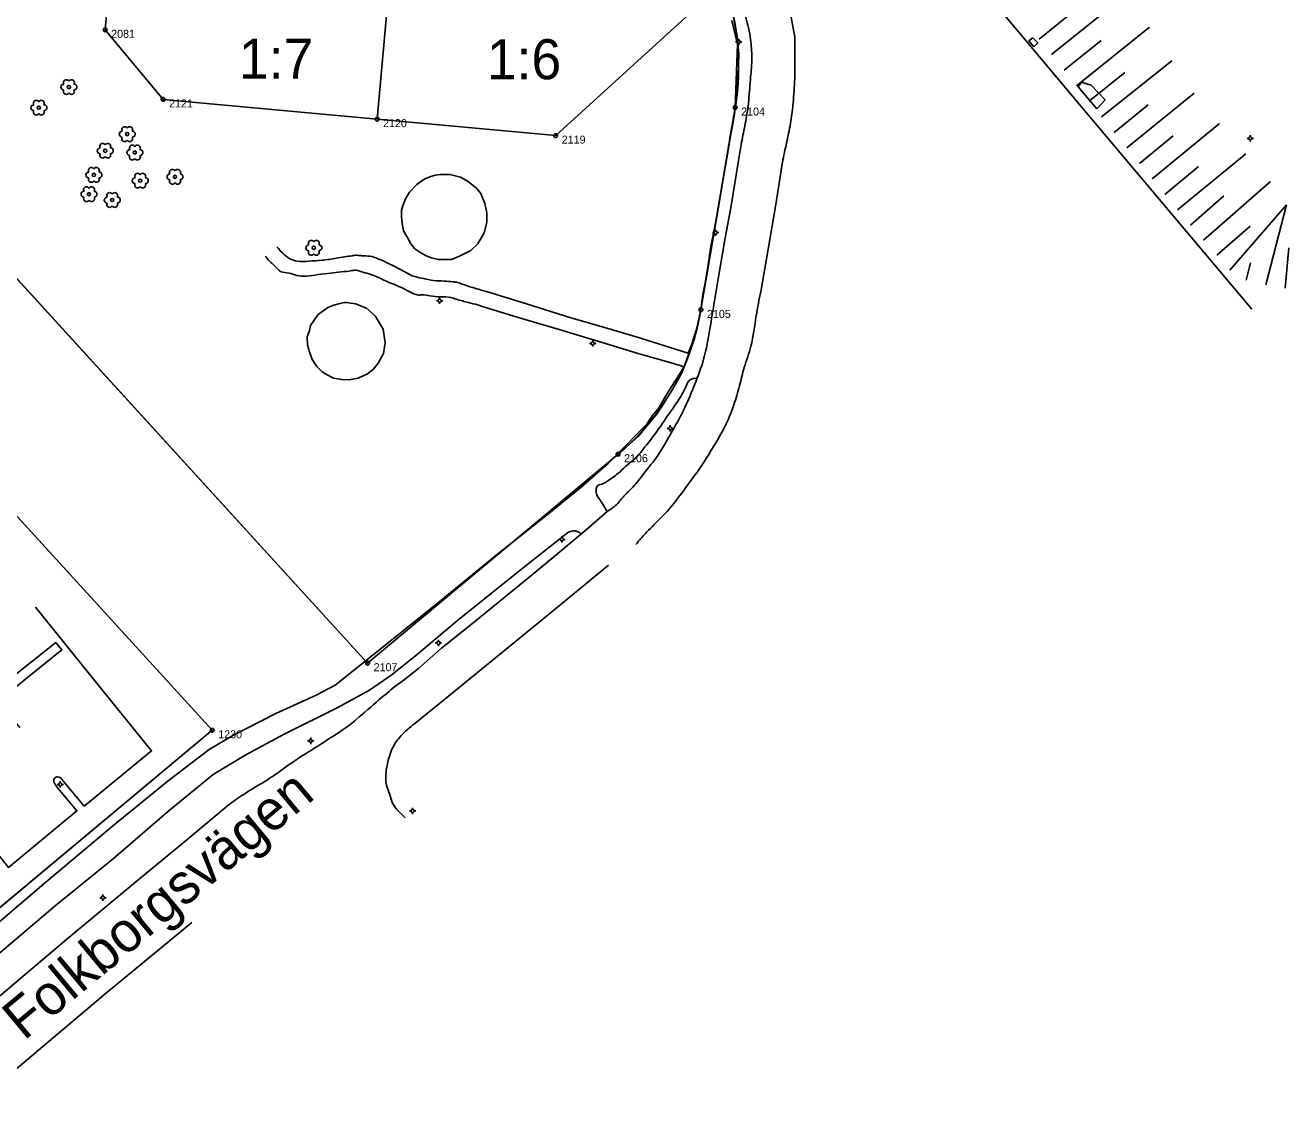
# Model space of a CAD drawing. Extents: x 1517478 to 1518189, y 6494860 to 6495389.
# Drawn here: x 1518031.3 to 1518189.2, y 6494972.1 to 6495107.4 of the extents above; entities that cross this region are included whole.
import ezdxf

# ---------------------------------------------------------------- set-up
doc = ezdxf.new("R2010")
doc.units = 0
for name, color, linetype in [('fastighetsbeteckning', 7, 'Continuous'), ('gatunamn', 7, 'Continuous'), ('gc_vag', 7, 'Continuous'), ('grans', 7, 'Continuous'), ('granspunkt', 7, 'Continuous'), ('granspunkt_text', 7, 'Continuous'), ('kvartersgrans', 7, 'Continuous'), ('kvartersgrans_utan_fastgr', 7, 'Continuous'), ('kvartersytor', 7, 'Continuous'), ('lovtrad', 7, 'Continuous'), ('parkeringskant', 7, 'Continuous'), ('planteringskant', 7, 'Continuous'), ('slant_skraffering', 7, 'Continuous'), ('staket', 7, 'Continuous'), ('stolpe_belysning', 7, 'Continuous'), ('vagkant', 7, 'Continuous')]:
    doc.layers.add(name, color=color, linetype=linetype)

msp = doc.modelspace()

# ---------------------------------------------------------------- linework, layer by layer
at = {"layer": 'gc_vag'}
for points in [[(1518118.38, 6495087.34), (1518118.71, 6495089.22), (1518119.1, 6495091.32), (1518119.41, 6495093.33), (1518119.63, 6495094.49)], [(1518116.59, 6495076.95), (1518117.01, 6495079.78), (1518117.66, 6495083.14), (1518118.07, 6495085.6), (1518118.38, 6495087.34)], [(1518108.34, 6495068.28), (1518114.17, 6495066.44), (1518114.67, 6495067.72), (1518115.19, 6495069.34), (1518115.54, 6495070.77), (1518115.78, 6495072.17), (1518116, 6495073.78), (1518116.31, 6495075.24), (1518116.59, 6495076.95)], [(1518089.11, 6495074.12), (1518093.31, 6495072.82), (1518099.4, 6495070.92), (1518104, 6495069.59), (1518108.36, 6495068.28)], [(1518088.71, 6495072.21), (1518092.82, 6495070.95), (1518098.04, 6495069.4), (1518103.85, 6495067.66), (1518108.04, 6495066.38)], [(1518108.04, 6495066.38), (1518111.18, 6495065.48), (1518113.3, 6495064.86), (1518113.64, 6495064.7), (1518112.86, 6495063.49), (1518112.15, 6495062.31), (1518111.37, 6495061.1), (1518110.56, 6495059.64), (1518109.72, 6495058.67), (1518108.98, 6495057.52), (1518108.11, 6495056.71)], [(1518070.06, 6495024.95), (1518076.25, 6495029.91), (1518083.28, 6495035.51), (1518090.37, 6495041.36), (1518096.55, 6495046.25), (1518100.78, 6495049.7), (1518104.23, 6495052.69), (1518108.11, 6495056.71)], [(1518099.11, 6495043.98), (1518092.97, 6495039.15), (1518085.36, 6495033.03), (1518080.35, 6495028.8), (1518077.16, 6495026.26), (1518074.33, 6495024.31)], [(1518049.18, 6495012.98), (1518054.3, 6495016.9), (1518057.26, 6495018.64), (1518062.65, 6495021.42), (1518067.69, 6495023.69), (1518070.06, 6495024.95)], [(1518049.31, 6495009.27), (1518054.82, 6495013.77), (1518058.82, 6495016.21), (1518063.69, 6495018.82), (1518070.3, 6495022.12), (1518074.33, 6495024.31)], [(1518018.32, 6494987.11), (1518024.97, 6494992.73), (1518033.63, 6495000.09), (1518042.48, 6495007.51), (1518049.18, 6495012.98)], [(1518025.3, 6494989.09), (1518035.06, 6494997.36), (1518042.35, 6495003.28), (1518049.31, 6495009.27)]]:
    msp.add_lwpolyline(points, dxfattribs=at)
for points in [[(1518112.4, 6495123.17), (1518115.62, 6495119.07), (1518117.64, 6495115.15), (1518118.65, 6495112.85), (1518119.88, 6495108.19), (1518120.44, 6495104.77), (1518120.39, 6495101.02)], [(1518120.39, 6495101.02), (1518120.02, 6495096.76), (1518119.35, 6495093.11), (1518118.85, 6495090.03)], [(1518062.77, 6495079.75), (1518063.52, 6495078.94), (1518064.39, 6495078.26), (1518065.32, 6495077.95), (1518066.75, 6495077.95), (1518068.43, 6495078.07), (1518070.17, 6495078.32), (1518071.23, 6495078.51), (1518072.16, 6495078.63), (1518072.78, 6495078.69), (1518073.4, 6495078.63), (1518074.4, 6495078.57), (1518075.39, 6495078.26), (1518076.32, 6495077.89)], [(1518088.99, 6495072.13), (1518086.72, 6495072.79), (1518085.2, 6495073.19), (1518084.51, 6495073.41), (1518083.27, 6495073.5), (1518081.87, 6495073.63), (1518080.97, 6495073.75), (1518080.47, 6495073.72), (1518079.88, 6495073.88), (1518078.58, 6495074.53), (1518076.65, 6495075.37), (1518074.29, 6495076.36), (1518073.26, 6495076.67), (1518072.74, 6495076.83), (1518072.14, 6495076.77), (1518070.78, 6495076.61), (1518069.5, 6495076.46), (1518067.92, 6495076.27), (1518066.49, 6495076.08), (1518065.28, 6495076.18), (1518064.28, 6495076.46), (1518063.29, 6495076.64), (1518062.85, 6495076.98), (1518062.17, 6495077.67), (1518061.8, 6495078.01), (1518061.36, 6495078.57)], [(1518076.25, 6495077.92), (1518078.76, 6495076.61), (1518080.01, 6495076.02), (1518081.13, 6495075.77), (1518082.34, 6495075.55), (1518083.64, 6495075.46), (1518084.76, 6495075.37), (1518085.35, 6495075.28), (1518086.1, 6495075.03), (1518087.96, 6495074.44), (1518089.3, 6495074.06)], [(1518104.03, 6495046.64), (1518103.2, 6495048.02), (1518102.76, 6495048.73), (1518102.66, 6495049.33), (1518102.82, 6495049.85), (1518103.37, 6495050.09), (1518104.49, 6495050.72), (1518105.66, 6495051.63), (1518106.59, 6495052.5), (1518107.55, 6495053.3), (1518108.56, 6495054.45), (1518110.25, 6495056.66), (1518112, 6495059.2), (1518113.24, 6495061.03), (1518113.82, 6495062.13), (1518114.48, 6495063.17), (1518114.93, 6495063.3), (1518115.29, 6495063.32)], [(1518100.81, 6495043.84), (1518100.4, 6495044.12), (1518099.93, 6495044.23), (1518099.36, 6495044.12), (1518099.11, 6495043.98)]]:
    msp.add_spline(points, degree=3, dxfattribs=at)
at = {"layer": 'grans'}
for p, q in [((1517942.78, 6495142.01), (1518054.69, 6495019.3)), ((1518041.31, 6495106.88), (1518042.65, 6495121.42)), ((1518077.26, 6495117.12), (1518075.29, 6495095.71)), ((1518118.64, 6495112.82), (1518097.62, 6495093.65)), ((1518048.54, 6495098.18), (1518041.31, 6495106.88)), ((1518075.29, 6495095.71), (1518048.54, 6495098.18)), ((1518097.62, 6495093.65), (1518075.29, 6495095.71)), ((1517998.49, 6494972.4), (1518054.69, 6495019.3))]:
    msp.add_line(p, q, dxfattribs=at)
at = {"layer": 'granspunkt'}
for centre in [(1518041.31, 6495106.88), (1518048.54, 6495098.18), (1518120.04, 6495097.16), (1518075.29, 6495095.71), (1518097.62, 6495093.65), (1518115.77, 6495071.86), (1518105.41, 6495053.82), (1518074.11, 6495027.69), (1518054.69, 6495019.3)]:
    msp.add_circle(centre, 0.237, dxfattribs=at)
at = {"layer": 'kvartersgrans'}
msp.add_line((1517998.49, 6494972.4), (1518054.69, 6495019.3), dxfattribs=at)
msp.add_lwpolyline([(1517905.68, 6495182.68), (1517942.78, 6495142.01), (1518054.69, 6495019.3)], dxfattribs=at)
at = {"layer": 'kvartersgrans_utan_fastgr'}
for p, q in [((1517921.04, 6495195.52), (1518074.11, 6495027.69)), ((1518115.77, 6495071.86), (1518120.04, 6495097.16)), ((1518074.11, 6495027.69), (1518105.41, 6495053.82))]:
    msp.add_line(p, q, dxfattribs=at)
for centre, radius, start, end in [((1518089.47, 6495102.32), 31.01, 350.4256, 19.8012), ((1518086.18, 6495076.85), 30.01, 309.8505, 350.4132)]:
    msp.add_arc(centre, radius, start, end, dxfattribs=at)
at = {"layer": 'kvartersytor'}
for points in [[(1518119.61, 6495108.06), (1518120.35, 6495105.08), (1518120.04, 6495097.16), (1518117.91, 6495084.51), (1518115.77, 6495071.86), (1518114.98, 6495068.27), (1518113.39, 6495063.98), (1518112.21, 6495061.91), (1518110.29, 6495058.89), (1518107.91, 6495056.05), (1518105.41, 6495053.81), (1518074.11, 6495027.69), (1517921.04, 6495195.52)], [(1517905.68, 6495182.68), (1518054.69, 6495019.3), (1517998.49, 6494972.4)]]:
    msp.add_lwpolyline(points, dxfattribs=at)
at = {"layer": 'lovtrad'}
for centre in [(1518036.78, 6495099.72), (1518033.02, 6495097.14), (1518044.06, 6495093.84), (1518041.32, 6495091.76), (1518045.02, 6495091.54), (1518039.9, 6495088.74), (1518045.69, 6495088.02), (1518050.04, 6495088.5), (1518039.29, 6495086.33), (1518042.19, 6495085.6), (1518067.38, 6495079.63)]:
    msp.add_circle(centre, 0.2, dxfattribs=at)
for centre, start, end in [((1518036.15, 6495099.72), 89.5389, 268.9887), ((1518036.46, 6495100.28), 29.1347, 212.3057), ((1518037.1, 6495100.28), 329.1331, 150.8613), ((1518037.42, 6495099.72), 269.1508, 90.8733), ((1518036.46, 6495099.17), 150.5831, 330.865), ((1518037.1, 6495099.17), 209.1844, 30.8583), ((1518032.39, 6495097.14), 89.5389, 268.9887), ((1518032.7, 6495097.7), 29.1347, 212.3057), ((1518033.34, 6495097.7), 329.1331, 150.8613), ((1518033.66, 6495097.14), 269.1508, 90.8733), ((1518032.7, 6495096.59), 150.5831, 330.865), ((1518033.34, 6495096.59), 209.1844, 30.8583), ((1518043.43, 6495093.83), 89.5389, 268.9887), ((1518043.75, 6495094.39), 29.1347, 212.3057), ((1518044.38, 6495094.39), 329.1331, 150.8613), ((1518044.7, 6495093.84), 269.1508, 90.8733), ((1518041, 6495092.31), 29.1347, 212.3057), ((1518041.64, 6495092.31), 329.1331, 150.8613), ((1518041.96, 6495091.76), 269.1508, 90.8733), ((1518043.75, 6495093.28), 150.5831, 330.865), ((1518044.38, 6495093.28), 209.1844, 30.8583), ((1518044.7, 6495092.09), 29.1347, 212.3057), ((1518045.34, 6495092.09), 329.1331, 150.8613), ((1518040.69, 6495091.75), 89.5389, 268.9887), ((1518041, 6495091.21), 150.5831, 330.865), ((1518041.64, 6495091.21), 209.1844, 30.8583), ((1518044.39, 6495091.53), 89.5389, 268.9887), ((1518044.7, 6495090.98), 150.5831, 330.865), ((1518045.34, 6495090.98), 209.1844, 30.8583), ((1518045.66, 6495091.54), 269.1508, 90.8733), ((1518039.27, 6495088.73), 89.5389, 268.9887), ((1518039.58, 6495089.3), 29.1347, 212.3057), ((1518040.22, 6495089.3), 329.1331, 150.8613), ((1518040.54, 6495088.74), 269.1508, 90.8733), ((1518049.72, 6495089.06), 29.1347, 212.3057), ((1518050.36, 6495089.06), 329.1331, 150.8613), ((1518039.58, 6495088.19), 150.5831, 330.865), ((1518040.22, 6495088.19), 209.1844, 30.8583), ((1518045.06, 6495088.01), 89.5389, 268.9887), ((1518045.37, 6495088.57), 29.1347, 212.3057), ((1518045.37, 6495087.47), 150.5831, 330.865), ((1518046.01, 6495088.57), 329.1331, 150.8613), ((1518046.01, 6495087.47), 209.1844, 30.8583), ((1518046.33, 6495088.02), 269.1508, 90.8733), ((1518049.41, 6495088.49), 89.5389, 268.9887), ((1518049.72, 6495087.95), 150.5831, 330.865), ((1518050.36, 6495087.95), 209.1844, 30.8583), ((1518050.68, 6495088.5), 269.1508, 90.8733), ((1518038.66, 6495086.32), 89.5389, 268.9887), ((1518038.98, 6495086.88), 29.1347, 212.3057), ((1518038.98, 6495085.77), 150.5831, 330.865), ((1518039.61, 6495086.88), 329.1331, 150.8613), ((1518039.61, 6495085.77), 209.1844, 30.8583), ((1518039.93, 6495086.33), 269.1508, 90.8733), ((1518041.56, 6495085.59), 89.5389, 268.9887), ((1518041.87, 6495086.16), 29.1347, 212.3057), ((1518042.51, 6495086.16), 329.1331, 150.8613), ((1518042.83, 6495085.6), 269.1508, 90.8733), ((1518041.87, 6495085.05), 150.5831, 330.865), ((1518042.51, 6495085.05), 209.1844, 30.8583), ((1518066.75, 6495079.62), 89.5389, 268.9887), ((1518067.07, 6495080.18), 29.1347, 212.3057), ((1518067.7, 6495080.18), 329.1331, 150.8613), ((1518068.02, 6495079.63), 269.1508, 90.8733), ((1518067.07, 6495079.07), 150.5831, 330.865), ((1518067.7, 6495079.07), 209.1844, 30.8583)]:
    msp.add_arc(centre, 0.366, start, end, dxfattribs=at)
at = {"layer": 'parkeringskant'}
msp.add_line((1518038.68, 6495009.83), (1518035.97, 6495013.08), dxfattribs=at)
for points in [[(1518032.61, 6495034.68), (1518040.56, 6495024.81), (1518047.12, 6495016.72), (1518038.68, 6495009.83)], [(1518030.63, 6495019.67), (1518027.91, 6495022.92), (1518031.59, 6495025.9), (1518035.89, 6495029.34), (1518035.13, 6495030.27), (1518030.69, 6495026.73), (1518027.22, 6495023.88), (1518024.37, 6495027.26)], [(1518026.19, 6495005.95), (1518029.24, 6495002.14), (1518037.78, 6495009.23), (1518035.4, 6495012.08)]]:
    msp.add_lwpolyline(points, dxfattribs=at)
msp.add_spline([(1518035.4, 6495012.08), (1518035.02, 6495012.62), (1518034.91, 6495012.95), (1518034.94, 6495013.22), (1518035.04, 6495013.36), (1518035.4, 6495013.47), (1518035.73, 6495013.36), (1518035.97, 6495013.08)], degree=3, dxfattribs=at)
at = {"layer": 'planteringskant'}
for points in [[(1518157.39, 6495104.74), (1518157.86, 6495105.24), (1518157.24, 6495105.86), (1518156.75, 6495105.51), (1518157.39, 6495104.74)], [(1518165.24, 6495096.98), (1518166.27, 6495098.14), (1518164.55, 6495099.95), (1518163.31, 6495100.33), (1518162.9, 6495099.77), (1518165.24, 6495096.98)], [(1518083.21, 6495088.81), (1518084.39, 6495088.81), (1518085.71, 6495088.47), (1518086.68, 6495087.93), (1518087.74, 6495087.02), (1518088.28, 6495086.42), (1518088.76, 6495085.18), (1518089, 6495084), (1518089, 6495082.77), (1518088.67, 6495081.5), (1518087.89, 6495080.14), (1518087.01, 6495079.29), (1518085.53, 6495078.54), (1518084.54, 6495078.18), (1518083.69, 6495078.15), (1518082.97, 6495078.18), (1518082.09, 6495078.36), (1518081.43, 6495078.63), (1518080.64, 6495079.08), (1518080.01, 6495079.51), (1518079.53, 6495080.14), (1518079.14, 6495080.83), (1518078.59, 6495081.74), (1518078.41, 6495082.65), (1518078.35, 6495083.55), (1518078.35, 6495084.34), (1518078.53, 6495084.91), (1518078.86, 6495085.73), (1518079.35, 6495086.6), (1518080.31, 6495087.6), (1518081.25, 6495088.23), (1518082, 6495088.56), (1518082.61, 6495088.71), (1518083.18, 6495088.81), (1518083.18, 6495088.81)], [(1518071.45, 6495072.8), (1518072.6, 6495072.62), (1518073.96, 6495072.08), (1518075.05, 6495071.14), (1518076.07, 6495069.45), (1518076.31, 6495067.76), (1518076.1, 6495066.4), (1518075.44, 6495065.22), (1518074.86, 6495064.47), (1518074.11, 6495063.87), (1518072.93, 6495063.32), (1518071.79, 6495063.11), (1518070.88, 6495063.14), (1518069.86, 6495063.32), (1518069.07, 6495063.74), (1518068.44, 6495064.11), (1518067.77, 6495064.77), (1518067.2, 6495065.65), (1518066.84, 6495066.61), (1518066.6, 6495067.46), (1518066.57, 6495068.48), (1518066.84, 6495069.27), (1518066.99, 6495069.9), (1518067.5, 6495070.69), (1518067.95, 6495071.29), (1518068.53, 6495071.71), (1518069.13, 6495072.17), (1518069.89, 6495072.44), (1518070.64, 6495072.65), (1518071.21, 6495072.77), (1518071.55, 6495072.77)]]:
    msp.add_lwpolyline(points, dxfattribs=at)
at = {"layer": 'slant_skraffering'}
for p, q in [((1518159.58, 6495103.78), (1518168.86, 6495111.24)), ((1518158.02, 6495105.73), (1518162.67, 6495109.47)), ((1518162.71, 6495099.89), (1518171.84, 6495107.22)), ((1518161.15, 6495101.83), (1518165.77, 6495105.55)), ((1518165.84, 6495095.99), (1518174.6, 6495103.02)), ((1518164.28, 6495097.94), (1518168.75, 6495101.53)), ((1518169, 6495092.11), (1518177.41, 6495098.96)), ((1518167.42, 6495094.05), (1518171.68, 6495097.52)), ((1518172.16, 6495088.23), (1518180.58, 6495095.15)), ((1518170.58, 6495090.17), (1518174.79, 6495093.61)), ((1518175.34, 6495084.37), (1518183.85, 6495091.37)), ((1518173.75, 6495086.3), (1518177.97, 6495089.77)), ((1518178.58, 6495080.57), (1518186.94, 6495087.9)), ((1518176.93, 6495082.44), (1518181.1, 6495086.11)), ((1518181.87, 6495076.81), (1518188.94, 6495085)), ((1518186.35, 6495075), (1518188.94, 6495085)), ((1518180.23, 6495078.69), (1518184.41, 6495082.35)), ((1518188.8, 6495074.57), (1518189.23, 6495079.64)), ((1518183.91, 6495075.58), (1518184.43, 6495077.74))]:
    msp.add_line(p, q, dxfattribs=at)
at = {"layer": 'staket'}
msp.add_lwpolyline([(1518140.54, 6495124.4), (1518154.39, 6495107.9), (1518164.18, 6495096.23), (1518184.61, 6495071.96)], dxfattribs=at)
at = {"layer": 'stolpe_belysning'}
for p, q in [((1518120.29, 6495105.37), (1518120.09, 6495105.37)), ((1518120.49, 6495105.57), (1518120.49, 6495105.77)), ((1518120.49, 6495105.17), (1518120.49, 6495104.97)), ((1518120.69, 6495105.37), (1518120.89, 6495105.37)), ((1518184.42, 6495093.51), (1518184.42, 6495093.71)), ((1518184.22, 6495093.31), (1518184.02, 6495093.31)), ((1518184.42, 6495093.11), (1518184.42, 6495092.91)), ((1518184.62, 6495093.31), (1518184.82, 6495093.31)), ((1518117.4, 6495081.53), (1518117.2, 6495081.53)), ((1518117.6, 6495081.73), (1518117.6, 6495081.93)), ((1518117.6, 6495081.33), (1518117.6, 6495081.13)), ((1518117.8, 6495081.53), (1518118, 6495081.53)), ((1518083.11, 6495073.2), (1518083.11, 6495073.4)), ((1518082.91, 6495073), (1518082.71, 6495073)), ((1518083.11, 6495072.8), (1518083.11, 6495072.6)), ((1518083.31, 6495073), (1518083.51, 6495073)), ((1518102.04, 6495067.67), (1518101.84, 6495067.67)), ((1518102.24, 6495067.87), (1518102.24, 6495068.07)), ((1518102.24, 6495067.47), (1518102.24, 6495067.27)), ((1518102.44, 6495067.67), (1518102.64, 6495067.67)), ((1518111.94, 6495057.25), (1518111.94, 6495057.45)), ((1518111.74, 6495057.05), (1518111.54, 6495057.05)), ((1518111.94, 6495056.85), (1518111.94, 6495056.65)), ((1518112.14, 6495057.05), (1518112.34, 6495057.05)), ((1518098.4, 6495043.36), (1518098.4, 6495043.56)), ((1518098.2, 6495043.16), (1518098, 6495043.16)), ((1518098.4, 6495042.96), (1518098.4, 6495042.76)), ((1518098.6, 6495043.16), (1518098.8, 6495043.16)), ((1518082.96, 6495030.43), (1518082.96, 6495030.63)), ((1518082.76, 6495030.23), (1518082.56, 6495030.23)), ((1518082.96, 6495030.03), (1518082.96, 6495029.83)), ((1518083.16, 6495030.23), (1518083.36, 6495030.23)), ((1518066.8, 6495017.98), (1518066.6, 6495017.98)), ((1518067, 6495018.18), (1518067, 6495018.38)), ((1518067.2, 6495017.98), (1518067.4, 6495017.98)), ((1518067, 6495017.78), (1518067, 6495017.58)), ((1518035.5, 6495012.54), (1518035.3, 6495012.54)), ((1518035.7, 6495012.74), (1518035.7, 6495012.94)), ((1518035.7, 6495012.34), (1518035.7, 6495012.14)), ((1518035.9, 6495012.54), (1518036.1, 6495012.54)), ((1518079.53, 6495009.22), (1518079.33, 6495009.22)), ((1518079.73, 6495009.42), (1518079.73, 6495009.62)), ((1518079.73, 6495009.02), (1518079.73, 6495008.82)), ((1518079.93, 6495009.22), (1518080.13, 6495009.22)), ((1518040.83, 6494998.37), (1518040.63, 6494998.37)), ((1518041.03, 6494998.57), (1518041.03, 6494998.77)), ((1518041.03, 6494998.17), (1518041.03, 6494997.97)), ((1518041.23, 6494998.37), (1518041.43, 6494998.37))]:
    msp.add_line(p, q, dxfattribs=at)
for centre in [(1518120.49, 6495105.37), (1518184.42, 6495093.31), (1518117.6, 6495081.53), (1518083.11, 6495073), (1518102.24, 6495067.67), (1518111.94, 6495057.05), (1518098.4, 6495043.16), (1518082.96, 6495030.23), (1518067, 6495017.98), (1518035.7, 6495012.54), (1518079.73, 6495009.22), (1518041.03, 6494998.37)]:
    msp.add_circle(centre, 0.2, dxfattribs=at)
at = {"layer": 'vagkant'}
for points in [[(1518120.47, 6495090.56), (1518119.53, 6495084.88), (1518118.75, 6495080.62), (1518117.94, 6495075.74), (1518117.47, 6495073)], [(1518126.02, 6495090.64), (1518125.12, 6495085.04), (1518124.16, 6495079.47), (1518123.25, 6495074.12)], [(1518104.03, 6495046.64), (1518101.43, 6495044.36), (1518098.63, 6495042.02), (1518095.18, 6495039.15), (1518090.63, 6495035.44), (1518087.05, 6495032.51), (1518083.34, 6495029.58), (1518080.48, 6495027.04), (1518078.53, 6495025.48), (1518077.52, 6495024.76)], [(1518080.24, 6495020.33), (1518084.9, 6495024.11), (1518091.67, 6495029.65), (1518098.31, 6495035.05), (1518104.23, 6495039.93)], [(1518025.31, 6494989.09), (1518027.77, 6494985.83), (1518036.75, 6494993.39), (1518044.89, 6495000.16), (1518051.52, 6495005.62), (1518056.86, 6495010.05)], [(1518052.14, 6494995.27), (1518041.28, 6494986.3), (1518033.54, 6494979.77), (1518024.45, 6494972.11)]]:
    msp.add_lwpolyline(points, dxfattribs=at)
for points in [[(1518118.6, 6495116.69), (1518119.77, 6495114.23), (1518120.52, 6495111.89), (1518121.29, 6495109.23), (1518121.38, 6495108.44), (1518121.73, 6495107.11), (1518121.97, 6495105.66), (1518122.13, 6495103.44), (1518122.04, 6495101.59), (1518121.92, 6495100.31)], [(1518124.44, 6495117.28), (1518125.53, 6495114.5), (1518126.25, 6495111.99), (1518126.83, 6495109.32), (1518127.22, 6495107.56), (1518127.5, 6495105.71), (1518127.5, 6495104.01), (1518127.5, 6495102.5), (1518127.5, 6495100.62)], [(1518121.92, 6495100.34), (1518121.65, 6495097.31), (1518121.25, 6495094.86), (1518120.8, 6495092.55), (1518120.47, 6495090.55)], [(1518127.5, 6495100.77), (1518127.29, 6495097.77), (1518127.01, 6495095.49), (1518126.53, 6495093.04), (1518126.01, 6495090.61)], [(1518123.26, 6495074.18), (1518122.67, 6495071.12), (1518122.02, 6495067.34), (1518121.18, 6495064.67), (1518120.59, 6495062.39), (1518119.88, 6495059.98), (1518118.71, 6495057.18), (1518117.14, 6495054.45), (1518115.84, 6495052.37), (1518114.09, 6495049.96), (1518112.13, 6495047.35), (1518110.51, 6495045.6), (1518108.82, 6495043.9), (1518107.64, 6495042.54)], [(1518117.47, 6495073), (1518116.88, 6495069.49), (1518116.1, 6495065.71), (1518115, 6495062.59), (1518113.76, 6495059.66), (1518112.78, 6495057.77), (1518111.68, 6495055.82), (1518110.38, 6495053.67), (1518108.62, 6495051.39), (1518107.25, 6495049.7), (1518106.15, 6495048.59), (1518105.24, 6495047.55), (1518104.02, 6495046.63)], [(1518056.85, 6495010.05), (1518059.23, 6495011.68), (1518061.58, 6495013.11), (1518063.46, 6495014.41), (1518065.74, 6495015.98), (1518067.69, 6495017.21), (1518069.51, 6495018.38), (1518071.01, 6495019.36), (1518072.7, 6495020.66), (1518075.57, 6495023.14), (1518077.52, 6495024.76)], [(1518080.25, 6495020.34), (1518078.43, 6495018.77), (1518077.39, 6495017.41), (1518076.74, 6495015.72), (1518076.41, 6495014.09), (1518076.48, 6495012.46), (1518076.87, 6495011.29), (1518077.26, 6495010.12), (1518077.78, 6495009.4), (1518078.82, 6495008.36)]]:
    msp.add_spline(points, degree=3, dxfattribs=at)

# ---------------------------------------------------------------- texts
at = {"layer": 'fastighetsbeteckning'}
for s, p in [('1:7', (1518058.02, 6495100.78)), ('1:6', (1518089.01, 6495100.7))]:
    msp.add_text(s, height=5, rotation=0.0021, dxfattribs=at).set_placement(p)
at = {"layer": 'gatunamn'}
msp.add_text('Folkborgsvägen', height=5, rotation=39.8263, dxfattribs=at).set_placement((1518031.17, 6494980.42))
at = {"layer": 'granspunkt_text'}
for s, p in [('2081', (1518042.06, 6495105.88)), ('2121', (1518049.29, 6495097.18)), ('2104', (1518120.79, 6495096.16)), ('2120', (1518076.04, 6495094.71)), ('2119', (1518098.37, 6495092.65)), ('2105', (1518116.52, 6495070.86)), ('2106', (1518106.16, 6495052.82)), ('2107', (1518074.86, 6495026.69)), ('1230', (1518055.44, 6495018.3))]:
    msp.add_text(s, height=1, dxfattribs=at).set_placement(p)

doc.saveas('drawing.dxf')
